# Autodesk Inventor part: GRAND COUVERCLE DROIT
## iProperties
Created: 2004-11
Part Number: GRAND COUVERCLE DROIT
Document SubType Name: Modeling
Designer: Bruno
Manufacturer: Standard
Standards Organization: Custom
Author: Bruno
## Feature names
1. Base1
